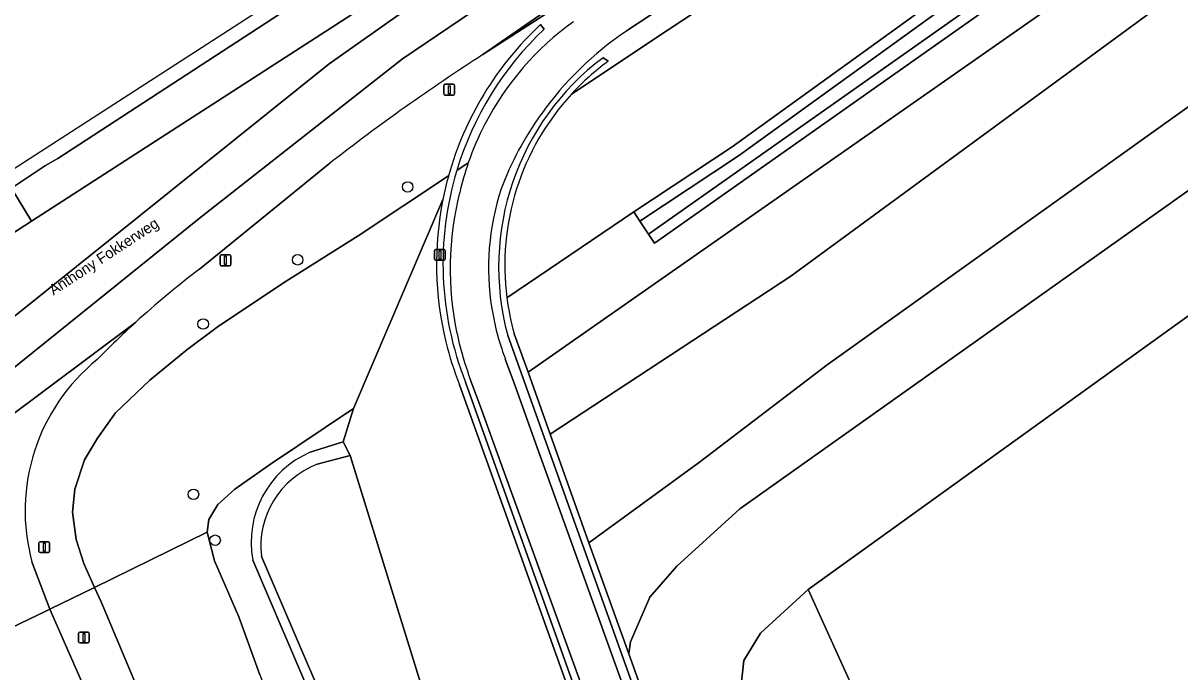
# Model space of a CAD drawing. Extents: x 156502 to 159075, y 384229 to 386100.
# Drawn here: x 156592.3 to 156699.9, y 385650.6 to 385710.9 of the extents above; entities that cross this region are included whole.
import ezdxf

# ---------------------------------------------------------------- set-up
doc = ezdxf.new("R2010")
doc.units = 0
for name, color, linetype in [('IMGEO_Berm_groen', 7, 'Continuous'), ('IMGEO_Boom', 7, 'Continuous'), ('IMGEO_Fietspad_gesloten', 7, 'Continuous'), ('IMGEO_Grasland_overig', 7, 'Continuous'), ('IMGEO_Groenvoorziening', 7, 'Continuous'), ('IMGEO_Haag', 7, 'Continuous'), ('IMGEO_Hek', 7, 'Continuous'), ('IMGEO_Lichtmast', 7, 'Continuous'), ('IMGEO_Loofbos', 7, 'Continuous'), ('IMGEO_Oever', 7, 'Continuous'), ('IMGEO_Openbare_ruimte_label', 7, 'Continuous'), ('IMGEO_Rijbaan_autoweg', 7, 'Continuous'), ('IMGEO_Rijbaan_regionaal_gesloten', 7, 'Continuous'), ('IMGEO_Rijbaan_regionaal_open', 7, 'Continuous'), ('IMGEO_Verkeerseiland_groen', 7, 'Continuous'), ('IMGEO_Verkeersregelinstallatiepaal', 7, 'Continuous'), ('IMGEO_Waterloop', 7, 'Continuous')]:
    doc.layers.add(name, color=color, linetype=linetype)

msp = doc.modelspace()

# ---------------------------------------------------------------- linework, layer by layer
at = {"layer": 'IMGEO_Berm_groen'}
for points in [[(156749.15, 385782.17), (156699.49, 385749.8), (156648.73, 385716.81), (156635.07, 385707.99)], [(156640.42, 385710.77), (156640.77, 385710.34)], [(156620.82, 385697.89), (156608.72, 385688.05)], [(156632.64, 385697.21), (156633.7, 385697.92)], [(156600.9, 385674.67), (156604.1, 385677.72), (156607.53, 385680.53), (156610.49, 385682.74), (156616.78, 385686.91), (156623.47, 385691.12), (156631.87, 385696.71)], [(156618.99, 385671.01), (156622.07, 385671.98), (156623.02, 385675.08), (156615.23, 385669.86), (156612.01, 385667.6), (156610.4, 385666.16), (156609.58, 385664.78), (156609.43, 385663.6), (156610.09, 385660.91), (156612.38, 385655.73), (156614.32, 385650.33), (156617.77, 385641.73), (156620.92, 385634.45), (156622.89, 385630.72), (156626.98, 385621.94), (156628.46, 385618.72), (156632.82, 385608.22), (156636.99, 385597.74), (156641.02, 385587.6), (156644.37, 385578.77), (156647.3, 385570.64), (156649.73, 385562.14), (156652.43, 385553.49), (156655.19, 385545.2)], [(156593.12, 385660.83), (156594.79, 385656.42), (156598.95, 385658.46), (156598.83, 385658.73), (156597.95, 385660.68), (156597.24, 385662.91), (156596.91, 385665.45), (156597.11, 385667.59), (156598, 385670.31), (156599.21, 385672.33), (156600.9, 385674.67)], [(156677.95, 385494.53), (156674.73, 385501.39), (156672.53, 385506.64), (156668.81, 385516.9), (156665.19, 385527.94), (156664.52, 385529.89), (156669.3, 385531.52), (156654.49, 385568.05), (156653.09, 385567.34), (156652.22, 385566.89), (156648.39, 385577.29), (156637.51, 385604.76), (156631.53, 385619.15), (156618.03, 385650.77), (156613.67, 385661)], [(156603.26, 385648.36), (156599.57, 385657.1), (156598.95, 385658.46), (156594.79, 385656.42), (156598.06, 385649.04)]]:
    msp.add_lwpolyline(points, dxfattribs=at)
for centre, radius, start, end in [((156661.18, 385688.51), 30.44, 133.0101, 164.3829), ((156659.26, 385689.08), 27.04, 125.7042, 152.5869), ((156661.29, 385688.54), 29.94, 133.2726, 163.1579), ((156739.38, 385545.74), 192.88, 122.7381, 127.9285), ((156659.62, 385688.91), 27.44, 152.6203, 160.8293), ((156660.51, 385619.86), 85.63, 127.2178, 132.4142), ((156660.35, 385619.98), 85.43, 132.3883, 135.7183), ((156610.56, 385665.58), 18.07, 128.9845, 195.2482), ((156622.65, 385662.64), 9.14, 113.6111, 190.3391)]:
    msp.add_arc(centre, radius, start, end, dxfattribs=at)
at = {"layer": 'IMGEO_Boom'}
for centre in [(156628.07, 385695.68), (156617.84, 385688.91), (156609.05, 385682.94), (156608.15, 385667.11), (156610.16, 385662.84)]:
    msp.add_circle(centre, 0.489, dxfattribs=at)
at = {"layer": 'IMGEO_Fietspad_gesloten'}
for points in [[(156648.43, 385710.2), (156659.36, 385717.42), (156708.86, 385750), (156753.13, 385778.55)], [(156675.33, 385574.38), (156675.23, 385574.61), (156655.22, 385629.6), (156643.65, 385661.67), (156639.99, 385671.81), (156637.93, 385677.52), (156637.15, 385679.66)], [(156633.89, 385677.82), (156634.43, 385676.33), (156634.8, 385675.33), (156636.83, 385669.74), (156640.76, 385658.91), (156651.82, 385628.48), (156670.43, 385577.01)]]:
    msp.add_lwpolyline(points, dxfattribs=at)
for centre, radius, start, end in [((156659.26, 385689.08), 27.04, 125.7042, 152.5869), ((156665.86, 385684.39), 31.14, 124.0201, 144.6192), ((156665.84, 385684.38), 31.14, 144.5922, 159.0539), ((156659.62, 385688.91), 27.44, 152.6203, 160.8293), ((156659.3, 385689.07), 27.08, 160.914, 167.0597), ((156659.35, 385688.13), 23.76, 161.9028, 189.0873), ((156661.01, 385688.06), 28.99, 165.8665, 191.9715), ((156659.3, 385688.12), 23.7, 189.0889, 198.4368), ((156661.06, 385688.07), 29.03, 191.9838, 199.2948), ((156658.73, 385687.92), 23.1, 198.4016, 200.9437), ((156670.1, 385691.36), 38.66, 199.472, 200.5082)]:
    msp.add_arc(centre, radius, start, end, dxfattribs=at)
at = {"layer": 'IMGEO_Grasland_overig'}
msp.add_lwpolyline([(156614.32, 385650.33), (156612.38, 385655.73), (156610.09, 385660.91), (156609.43, 385663.6), (156598.95, 385658.46), (156599.57, 385657.1), (156603.26, 385648.36)], dxfattribs=at)
at = {"layer": 'IMGEO_Groenvoorziening'}
for points in [[(156799.05, 385807.82), (156788.68, 385800.45), (156786.11, 385798.7), (156761.01, 385781.57), (156712.54, 385750), (156652.3, 385710.29), (156643.29, 385704.3)], [(156637.3, 385685.36), (156649.11, 385693.35), (156658.26, 385699.4), (156728.34, 385750)], [(156640.77, 385710.34), (156640.42, 385710.77)], [(156646.71, 385707.36), (156646.23, 385707.7)], [(156633.7, 385697.92), (156632.64, 385697.21)], [(156631.87, 385696.71), (156623.47, 385691.12), (156616.78, 385686.91), (156610.49, 385682.74), (156607.53, 385680.53), (156604.1, 385677.72), (156600.9, 385674.67), (156599.21, 385672.33), (156598, 385670.31), (156597.11, 385667.59), (156596.91, 385665.45), (156597.24, 385662.91), (156597.95, 385660.68), (156598.83, 385658.73), (156598.95, 385658.46), (156609.43, 385663.6), (156609.58, 385664.78), (156610.4, 385666.16), (156612.01, 385667.6), (156615.23, 385669.86), (156623.02, 385675.08), (156631.35, 385694.52)], [(156631.35, 385694.52), (156623.02, 385675.08), (156622.07, 385671.98), (156622.72, 385670.71), (156654.49, 385568.05), (156669.3, 385531.52), (156670.68, 385527.44), (156675, 385515.39), (156678.53, 385505.86), (156687.54, 385486.08), (156695.4, 385470.43), (156703.05, 385456.22), (156711.45, 385441.94), (156712.98, 385439.53), (156717.11, 385432.25), (156725.97, 385417.8), (156729.33, 385412.67), (156732.67, 385407.15), (156737.02, 385400.5), (156748.87, 385382.03), (156754.51, 385373.79), (156759.04, 385367.98), (156760.62, 385365.82), (156762.45, 385363.61)], [(156637.37, 385681.88), (156677.06, 385570.89), (156677.05, 385561.67), (156682.52, 385556.79), (156684.61, 385551.78), (156671.64, 385545.03), (156671.92, 385544.5), (156679.06, 385548.23), (156683.96, 385550.79), (156685.6, 385551.65), (156683.15, 385557.28), (156681.4, 385558.77), (156677.7, 385561.93), (156677.71, 385570.28), (156677.72, 385571.04), (156648.63, 385652.28), (156644.93, 385662.6)], [(156644.93, 385662.6), (156641.32, 385672.69), (156639.26, 385678.45), (156637.97, 385682.04)], [(156632.9, 385677.28), (156650.07, 385629.36), (156669.96, 385574.02)], [(156669.96, 385574.02), (156650.07, 385629.36), (156632.9, 385677.28)], [(156670.51, 385574.18), (156650.55, 385629.62), (156633.45, 385677.54)], [(156633.45, 385677.54), (156650.55, 385629.62), (156670.51, 385574.18)], [(156670.43, 385577.01), (156651.82, 385628.48), (156640.76, 385658.91), (156636.83, 385669.74), (156634.8, 385675.33), (156634.43, 385676.33), (156633.89, 385677.82)], [(156699.83, 385544.75), (156667.09, 385647.34), (156669.86, 385648.22), (156665.32, 385658.26), (156660.88, 385654.21), (156659.33, 385651.66), (156659, 385648.51), (156665.24, 385632.57), (156675.63, 385603.61), (156682.22, 385583.57), (156688.22, 385562.21), (156695.89, 385539.64)]]:
    msp.add_lwpolyline(points, dxfattribs=at)
for centre, radius, start, end in [((156661.18, 385688.51), 30.44, 133.0101, 164.3829), ((156661.29, 385688.54), 29.94, 133.2726, 163.1579), ((156660.88, 385688.24), 24.35, 126.9671, 195.1395), ((156660.6, 385688.44), 23.47, 126.2616, 137.4903), ((156660.64, 385688.39), 23.54, 137.4697, 187.3932), ((156660.64, 385688.39), 23.54, 137.4697, 187.3932), ((156659.3, 385689.07), 27.08, 160.914, 167.0597), ((156661.28, 385688.54), 29.93, 163.1451, 201.5634), ((156661.28, 385688.54), 29.93, 163.1451, 201.5634), ((156660.95, 385688.58), 30.2, 164.377, 168.6493), ((156660.95, 385688.58), 30.2, 164.377, 168.6493), ((156661.19, 385688.51), 30.44, 168.6215, 193.7176), ((156661.19, 385688.51), 30.44, 168.6215, 193.7176), ((156661.01, 385688.06), 28.99, 165.8665, 191.9715), ((156660.71, 385688.4), 23.61, 187.3968, 195.6149), ((156661.06, 385688.07), 29.03, 191.9838, 199.2948), ((156661.19, 385688.51), 30.44, 193.716, 201.6479), ((156661.19, 385688.51), 30.44, 193.716, 201.6479), ((156670.1, 385691.36), 38.66, 199.472, 200.5082)]:
    msp.add_arc(centre, radius, start, end, dxfattribs=at)
at = {"layer": 'IMGEO_Haag'}
for points in [[(156640.77, 385710.34), (156640.42, 385710.77)], [(156646.71, 385707.36), (156646.23, 385707.7)], [(156637.37, 385681.88), (156677.06, 385570.89), (156677.05, 385561.67), (156682.52, 385556.79), (156684.61, 385551.78), (156671.64, 385545.03), (156671.92, 385544.5), (156679.06, 385548.23), (156683.96, 385550.79), (156685.6, 385551.65), (156683.15, 385557.28), (156681.4, 385558.77)], [(156681.4, 385558.77), (156677.7, 385561.93), (156677.71, 385570.28), (156677.72, 385571.04), (156648.63, 385652.28), (156644.93, 385662.6), (156641.32, 385672.69), (156639.26, 385678.45), (156637.97, 385682.04)], [(156632.9, 385677.28), (156650.07, 385629.36), (156669.96, 385574.02)], [(156670.51, 385574.18), (156650.55, 385629.62), (156633.45, 385677.54)]]:
    msp.add_lwpolyline(points, dxfattribs=at)
for centre, radius, start, end in [((156661.18, 385688.51), 30.44, 133.0101, 164.3829), ((156661.29, 385688.54), 29.94, 133.2726, 163.1579), ((156660.88, 385688.24), 24.35, 126.9671, 195.1395), ((156660.6, 385688.44), 23.47, 126.2616, 137.4903), ((156660.64, 385688.39), 23.54, 137.4697, 187.3932), ((156661.28, 385688.54), 29.93, 163.1451, 201.5634), ((156660.95, 385688.58), 30.2, 164.377, 168.6493), ((156661.19, 385688.51), 30.44, 168.6215, 193.7176), ((156660.71, 385688.4), 23.61, 187.3968, 195.6149), ((156661.19, 385688.51), 30.44, 193.716, 201.6479)]:
    msp.add_arc(centre, radius, start, end, dxfattribs=at)
at = {"layer": 'IMGEO_Hek'}
msp.add_lwpolyline([(156741.65, 385750), (156658.92, 385692.19)], dxfattribs=at)
at = {"layer": 'IMGEO_Lichtmast'}
for p, q in [((156631.44, 385704.32), (156631.44, 385705.12)), ((156631.44, 385705.12), (156631.44, 385704.32)), ((156631.54, 385705.22), (156632.33, 385705.22)), ((156632.33, 385705.22), (156631.54, 385705.22)), ((156632.43, 385705.12), (156632.43, 385704.32)), ((156632.43, 385704.32), (156632.43, 385705.12)), ((156632.33, 385704.22), (156631.54, 385704.22)), ((156631.54, 385704.22), (156632.33, 385704.22)), ((156610.62, 385688.46), (156610.62, 385689.26)), ((156610.62, 385689.26), (156610.62, 385688.46)), ((156610.72, 385689.36), (156611.51, 385689.36)), ((156611.51, 385689.36), (156610.72, 385689.36)), ((156611.61, 385689.26), (156611.61, 385688.46)), ((156611.61, 385688.46), (156611.61, 385689.26)), ((156630.57, 385688.96), (156630.57, 385689.76)), ((156630.57, 385689.76), (156630.57, 385688.96)), ((156630.67, 385689.86), (156631.46, 385689.86)), ((156631.46, 385689.86), (156630.67, 385689.86)), ((156631.56, 385689.76), (156631.56, 385688.96)), ((156631.56, 385688.96), (156631.56, 385689.76)), ((156611.51, 385688.36), (156610.72, 385688.36)), ((156610.72, 385688.36), (156611.51, 385688.36)), ((156631.46, 385688.86), (156630.67, 385688.86)), ((156630.67, 385688.86), (156631.46, 385688.86)), ((156597.47, 385653.39), (156597.47, 385654.19)), ((156597.47, 385654.19), (156597.47, 385653.39)), ((156597.57, 385654.29), (156598.36, 385654.29)), ((156598.36, 385654.29), (156597.57, 385654.29)), ((156598.46, 385654.19), (156598.46, 385653.39)), ((156598.46, 385653.39), (156598.46, 385654.19)), ((156598.36, 385653.29), (156597.57, 385653.29)), ((156597.57, 385653.29), (156598.36, 385653.29))]:
    msp.add_line(p, q, dxfattribs=at)
for points in [[(156631.86, 385705.09), (156632.01, 385705.09), (156632.01, 385704.34), (156631.86, 385704.34), (156631.86, 385705.09)], [(156611.04, 385689.23), (156611.19, 385689.23), (156611.19, 385688.48), (156611.04, 385688.48), (156611.04, 385689.23)], [(156630.99, 385689.73), (156631.14, 385689.73), (156631.14, 385688.98), (156630.99, 385688.98), (156630.99, 385689.73)], [(156597.89, 385654.17), (156598.04, 385654.17), (156598.04, 385653.42), (156597.89, 385653.42), (156597.89, 385654.17)]]:
    msp.add_lwpolyline(points, dxfattribs=at)
for centre, start, end in [((156631.54, 385705.12), 90, 180), ((156631.54, 385705.12), 90, 180), ((156632.33, 385705.12), 0, 90), ((156632.33, 385705.12), 360, 90), ((156631.54, 385704.32), 180, 270), ((156631.54, 385704.32), 180, 270), ((156632.33, 385704.32), 270, 0), ((156632.33, 385704.32), 270, 0), ((156610.72, 385689.26), 90, 180), ((156610.72, 385689.26), 90, 180), ((156611.51, 385689.26), 0, 90), ((156611.51, 385689.26), 360, 90), ((156630.67, 385689.76), 90, 180), ((156630.67, 385689.76), 90, 180), ((156630.67, 385688.96), 180, 270), ((156630.67, 385688.96), 180, 270), ((156631.46, 385689.76), 0, 90), ((156631.46, 385689.76), 360, 90), ((156631.46, 385688.96), 270, 0), ((156631.46, 385688.96), 270, 0), ((156610.72, 385688.46), 180, 270), ((156610.72, 385688.46), 180, 270), ((156611.51, 385688.46), 270, 0), ((156611.51, 385688.46), 270, 0), ((156597.57, 385654.19), 90, 180), ((156597.57, 385654.19), 90, 180), ((156597.57, 385653.39), 180, 270), ((156597.57, 385653.39), 180, 270), ((156598.36, 385654.19), 0, 90), ((156598.36, 385654.19), 360, 90), ((156598.36, 385653.39), 270, 0), ((156598.36, 385653.39), 270, 0)]:
    msp.add_arc(centre, 0.1, start, end, dxfattribs=at)
at = {"layer": 'IMGEO_Loofbos'}
for points in [[(156643.29, 385704.3), (156652.3, 385710.29), (156712.54, 385750), (156761.01, 385781.57), (156786.11, 385798.7), (156788.68, 385800.45), (156799.05, 385807.82)], [(156753.13, 385778.55), (156708.86, 385750), (156659.36, 385717.42), (156648.43, 385710.2)], [(156637.97, 385682.04), (156639.26, 385678.45), (156741.65, 385750), (156747.28, 385753.93), (156752.2, 385758.98)], [(156741.93, 385754.71), (156735.54, 385750), (156651.12, 385690.5), (156651.03, 385690.44), (156650.47, 385691.28), (156649.66, 385692.51), (156649.11, 385693.35), (156637.3, 385685.36)], [(156831.98, 385666.5), (156751.25, 385750), (156747.28, 385753.93), (156741.65, 385750), (156639.26, 385678.45), (156641.32, 385672.69), (156663.69, 385687.4), (156741.76, 385744.6), (156749.3, 385747.61), (156756.59, 385741.83), (156762.12, 385733.03), (156753.83, 385721.97), (156665.32, 385658.26), (156669.86, 385648.22), (156702.6, 385545.62)], [(156659, 385648.51), (156659.33, 385651.66), (156660.88, 385654.21), (156665.32, 385658.26), (156753.83, 385721.97), (156762.12, 385733.03), (156756.59, 385741.83), (156749.3, 385747.61), (156741.76, 385744.6), (156663.69, 385687.4), (156641.32, 385672.69), (156644.93, 385662.6), (156655.21, 385670.1), (156667.09, 385679.14), (156743.52, 385733.78), (156747.29, 385735.79), (156750.31, 385733.78), (156750.56, 385730.77), (156658.95, 385665.75), (156653.11, 385660.42), (156650.59, 385657.54), (156648.8, 385653.41), (156648.63, 385652.28), (156677.72, 385571.04)], [(156646.23, 385707.7), (156646.71, 385707.36)], [(156684.61, 385551.78), (156682.52, 385556.79), (156677.05, 385561.67), (156677.06, 385570.89), (156637.37, 385681.88)], [(156637.15, 385679.66), (156637.93, 385677.52), (156639.99, 385671.81), (156643.65, 385661.67), (156655.22, 385629.6), (156675.23, 385574.61), (156675.33, 385574.38)]]:
    msp.add_lwpolyline(points, dxfattribs=at)
msp.add_lwpolyline([(156750.56, 385730.77), (156750.31, 385733.78), (156747.29, 385735.79), (156743.52, 385733.78), (156667.09, 385679.14), (156655.21, 385670.1), (156644.93, 385662.6), (156648.63, 385652.28), (156648.8, 385653.41), (156650.59, 385657.54), (156653.11, 385660.42), (156658.95, 385665.75)], close=True, dxfattribs=at)
for centre, radius, start, end in [((156665.86, 385684.39), 31.14, 124.0201, 144.6192), ((156660.88, 385688.24), 24.35, 126.9671, 195.1395), ((156660.6, 385688.44), 23.47, 126.2616, 137.4903), ((156665.84, 385684.38), 31.14, 144.5922, 159.0539), ((156659.35, 385688.13), 23.76, 161.9028, 189.0873), ((156660.71, 385688.4), 23.61, 187.3968, 195.6149), ((156659.3, 385688.12), 23.7, 189.0889, 198.4368), ((156658.73, 385687.92), 23.1, 198.4016, 200.9437)]:
    msp.add_arc(centre, radius, start, end, dxfattribs=at)
at = {"layer": 'IMGEO_Oever'}
for points in [[(156739.88, 385758.41), (156728.34, 385750), (156658.26, 385699.4), (156649.11, 385693.35), (156649.66, 385692.51), (156658.83, 385698.58), (156728.93, 385749.19), (156740.28, 385757.46)], [(156741.33, 385755.55), (156734.95, 385750.82), (156650.47, 385691.28), (156651.03, 385690.44), (156651.12, 385690.5), (156735.54, 385750), (156741.93, 385754.71)], [(156622.72, 385670.71), (156622.07, 385671.98), (156618.99, 385671.01)], [(156619.66, 385669.9), (156622.72, 385670.71)], [(156613.67, 385661), (156618.03, 385650.77), (156631.53, 385619.15), (156637.51, 385604.76), (156648.39, 385577.29), (156652.22, 385566.89), (156653.09, 385567.34), (156654.49, 385568.05), (156652.62, 385567.73), (156649.31, 385577.68), (156638.38, 385605.12), (156632.38, 385619.56), (156614.47, 385661.34)]]:
    msp.add_lwpolyline(points, dxfattribs=at)
for centre, radius, start, end in [((156622.65, 385662.64), 9.14, 113.6111, 190.3391), ((156622.6, 385662.26), 8.19, 111.057, 186.4068)]:
    msp.add_arc(centre, radius, start, end, dxfattribs=at)
at = {"layer": 'IMGEO_Rijbaan_autoweg'}
msp.add_lwpolyline([(156645.79, 385545.39), (156643.02, 385552.41), (156640.52, 385558.85), (156637.56, 385566.18), (156635.67, 385570.7), (156634.19, 385574.07), (156632.4, 385577.77), (156630.48, 385581.87), (156628.51, 385586.04), (156626.32, 385590.51), (156624.2, 385594.94), (156621.92, 385599.68), (156619.45, 385604.72), (156617.41, 385608.98), (156615.24, 385613.35), (156614.95, 385613.3), (156611.38, 385620.76), (156606.25, 385632.11), (156598.06, 385649.04), (156594.79, 385656.42), (156594.42, 385656.24), (156583.22, 385650.88)], dxfattribs=at)
at = {"layer": 'IMGEO_Rijbaan_regionaal_gesloten'}
for points in [[(156765.7, 385802.07), (156756.82, 385796.07), (156749.55, 385791.22), (156730.97, 385779.04), (156686.2, 385750), (156628.33, 385712.45), (156620.77, 385707.13), (156591.48, 385683.65)], [(156722.7, 385782.03), (156590.51, 385696.73), (156591.23, 385695.55), (156594.39, 385697.66), (156595.53, 385698.33), (156654.09, 385736.45), (156698.33, 385764.9)], [(156716.04, 385765.09), (156702.77, 385756.55), (156686.14, 385745.74), (156672.85, 385737.15), (156656.24, 385726.4), (156636.3, 385713.49), (156627.6, 385707.58), (156608.84, 385692.88), (156589.82, 385677.58), (156582.82, 385672.19), (156580.79, 385670.76), (156582.31, 385667.8), (156602.76, 385683.08)], [(156635.07, 385707.99), (156649.78, 385718.19), (156698.01, 385749.42)], [(156578.61, 385675.01), (156580.79, 385670.76), (156582.82, 385672.19), (156589.82, 385677.58), (156608.84, 385692.88), (156627.6, 385707.58), (156636.3, 385713.49), (156656.24, 385726.4), (156672.85, 385737.15), (156686.14, 385745.74)], [(156608.72, 385688.05), (156620.82, 385697.89)], [(156579.63, 385683.78), (156593.08, 385692.5), (156591.23, 385695.55), (156590.51, 385696.73), (156548.97, 385669.92)], [(156602.76, 385683.08), (156582.31, 385667.8), (156576.57, 385663.51), (156577.79, 385660.86), (156583.22, 385650.88), (156594.42, 385656.24), (156594.79, 385656.42), (156593.12, 385660.83)]]:
    msp.add_lwpolyline(points, dxfattribs=at)
msp.add_lwpolyline([(156743.1, 385793.88), (156742.59, 385793.55), (156734.39, 385788.25), (156731.96, 385786.67), (156728.73, 385784.57), (156726.52, 385783.11), (156723.54, 385781.22), (156721.03, 385779.59), (156716.74, 385776.8), (156714.54, 385775.36), (156706.5, 385770.16), (156698.33, 385764.9), (156654.09, 385736.45), (156595.53, 385698.33), (156594.39, 385697.66), (156591.23, 385695.55), (156593.08, 385692.5), (156599.9, 385696.91), (156656.31, 385733.31), (156699.34, 385761.12), (156719.11, 385773.89)], close=True, dxfattribs=at)
for centre, radius, start, end in [((156739.38, 385545.74), 192.88, 122.7381, 127.9285), ((156660.51, 385619.86), 85.63, 127.2178, 132.4142), ((156660.35, 385619.98), 85.43, 132.3883, 135.7183), ((156610.56, 385665.58), 18.07, 128.9845, 195.2482)]:
    msp.add_arc(centre, radius, start, end, dxfattribs=at)
at = {"layer": 'IMGEO_Rijbaan_regionaal_open'}
msp.add_lwpolyline([(156770.53, 385796.42), (156770.3, 385796.74), (156748.42, 385782.2), (156698.01, 385749.42), (156649.78, 385718.19), (156635.07, 385707.99), (156648.73, 385716.81), (156699.49, 385749.8), (156749.15, 385782.17)], dxfattribs=at)
at = {"layer": 'IMGEO_Verkeerseiland_groen'}
for points in [[(156699.34, 385761.12), (156656.31, 385733.31), (156599.9, 385696.91), (156593.08, 385692.5), (156579.63, 385683.78)], [(156591.48, 385683.65), (156620.77, 385707.13), (156628.33, 385712.45)]]:
    msp.add_lwpolyline(points, dxfattribs=at)
at = {"layer": 'IMGEO_Verkeersregelinstallatiepaal'}
for p, q in [((156593.78, 385661.79), (156593.78, 385662.59)), ((156593.78, 385662.59), (156593.78, 385661.79)), ((156593.88, 385662.69), (156594.67, 385662.69)), ((156594.67, 385662.69), (156593.88, 385662.69)), ((156594.77, 385662.59), (156594.77, 385661.79)), ((156594.77, 385661.79), (156594.77, 385662.59)), ((156594.67, 385661.69), (156593.88, 385661.69)), ((156593.88, 385661.69), (156594.67, 385661.69))]:
    msp.add_line(p, q, dxfattribs=at)
msp.add_lwpolyline([(156594.2, 385662.56), (156594.35, 385662.56), (156594.35, 385661.81), (156594.2, 385661.81), (156594.2, 385662.56)], dxfattribs=at)
for centre, start, end in [((156593.88, 385662.59), 90, 180), ((156593.88, 385662.59), 90, 180), ((156594.67, 385662.59), 0, 90), ((156594.67, 385662.59), 360, 90), ((156593.88, 385661.79), 180, 270), ((156593.88, 385661.79), 180, 270), ((156594.67, 385661.79), 270, 0), ((156594.67, 385661.79), 270, 0)]:
    msp.add_arc(centre, 0.1, start, end, dxfattribs=at)
at = {"layer": 'IMGEO_Waterloop'}
for points in [[(156740.28, 385757.46), (156728.93, 385749.19), (156658.83, 385698.58), (156649.66, 385692.51), (156650.47, 385691.28), (156734.95, 385750.82), (156741.33, 385755.55)], [(156614.47, 385661.34), (156632.38, 385619.56), (156638.38, 385605.12), (156649.31, 385577.68), (156652.62, 385567.73), (156654.49, 385568.05), (156622.72, 385670.71)], [(156622.72, 385670.71), (156619.66, 385669.9)]]:
    msp.add_lwpolyline(points, dxfattribs=at)
msp.add_arc((156622.6, 385662.26), 8.19, 111.057, 186.4068, dxfattribs=at)

# ---------------------------------------------------------------- texts
at = {"layer": 'IMGEO_Openbare_ruimte_label'}
msp.add_text('Anthony Fokkerweg', height=1, rotation=33.1656, dxfattribs=at).set_placement((156595.13, 385685.57))

doc.saveas('drawing.dxf')
